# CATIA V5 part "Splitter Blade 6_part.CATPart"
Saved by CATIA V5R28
Part number: Splitter Blade 6_part
Definition: design
Nomenclature: Splitter Blade 6_part
Source: Unknown
Bounding box of the stored display mesh (mm): x -5.477 to -3.501, y 0.679 to 9.404, z 4.237 to 7.742
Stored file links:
  D:\paraturbo-cad\STEP\Turbocompressor_for_Christophe\Splitter Blade 6_part.CATPart
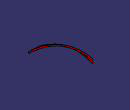
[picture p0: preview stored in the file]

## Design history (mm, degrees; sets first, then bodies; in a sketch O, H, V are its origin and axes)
Body1 "MANIFOLD_SOLID_BREP #71330" (main body)
  Solid1: solid without history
